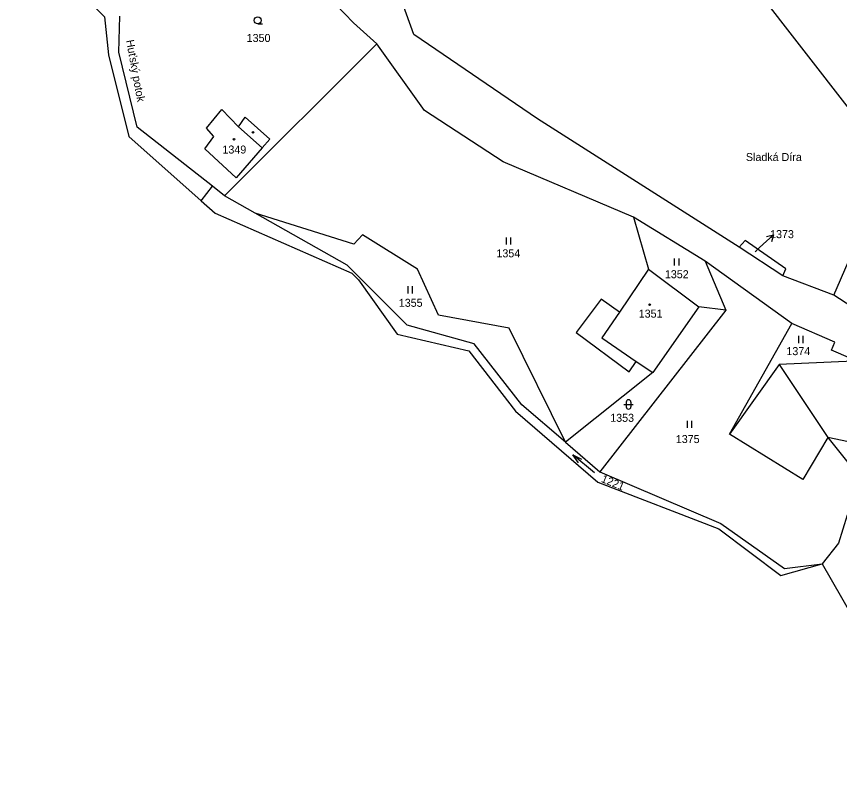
# Model space of a CAD drawing. Extents: x -670359 to -668019, y -978807 to -976674.
# Drawn here: x -669750.3 to -669575.5, y -978412.9 to -978251.2 of the extents above; entities that cross this region are included whole.
import ezdxf

# ---------------------------------------------------------------- set-up
doc = ezdxf.new("R2010")
doc.units = 0
for name, color, linetype in [('Hranice kat_území', 7, 'Continuous'), ('Hranice parcel', 7, 'Continuous'), ('Parcelní čísla', 7, 'Continuous'), ('Pop  PČ popisy', 7, 'Continuous'), ('Vnitřní kresba', 7, 'Continuous'), ('Značky budov', 7, 'Continuous'), ('Značky kultur', 7, 'Continuous')]:
    doc.layers.add(name, color=color, linetype=linetype)

msp = doc.modelspace()

# ---------------------------------------------------------------- linework, layer by layer
at = {"layer": 'Hranice kat_území'}
for points in [[(-669750.32, -978232.95), (-669731.63, -978251.32)], [(-669731.63, -978251.32), (-669730.74, -978259.36)], [(-669730.74, -978259.36), (-669726.47, -978276.74)], [(-669726.47, -978276.74), (-669711.08, -978290.39)], [(-669711.08, -978290.39), (-669708.1, -978293.03)], [(-669708.1, -978293.03), (-669679.08, -978305.78)], [(-669679.08, -978305.78), (-669677.68, -978307.17)], [(-669677.68, -978307.17), (-669669.42, -978318.74)], [(-669669.42, -978318.74), (-669654.21, -978322.24)], [(-669654.21, -978322.24), (-669644.3, -978335.07)], [(-669644.3, -978335.07), (-669626.85, -978350.14)], [(-669626.85, -978350.14), (-669601.13, -978360.04)], [(-669601.13, -978360.04), (-669587.99, -978369.95)], [(-669587.99, -978369.95), (-669579.21, -978367.53)], [(-669579.21, -978367.53), (-669553.11, -978412.89)]]:
    msp.add_lwpolyline(points, dxfattribs=at)
at = {"layer": 'Hranice parcel'}
for points in [[(-669572.87, -978271.54), (-669624.52, -978205.08)], [(-669678.72, -978252.62), (-669688.31, -978242.62)], [(-669665.94, -978255.08), (-669669.06, -978246.35)], [(-669728.54, -978258.84), (-669728.36, -978251.17)], [(-669673.74, -978257.07), (-669678.72, -978252.62)], [(-669639.64, -978272.98), (-669665.94, -978255.08)], [(-669673.74, -978257.07), (-669706.11, -978289.33)], [(-669663.64, -978271.2), (-669673.74, -978257.07)], [(-669724.71, -978274.79), (-669728.54, -978258.84)], [(-669709.95, -978274.94), (-669706.7, -978270.98)], [(-669706.7, -978270.98), (-669703.19, -978274.69)], [(-669646.94, -978282.1), (-669663.64, -978271.2)], [(-669703.19, -978274.69), (-669701.76, -978272.63)], [(-669701.76, -978272.63), (-669696.52, -978277.33)], [(-669596.79, -978300.24), (-669639.64, -978272.98)], [(-669708.68, -978287.32), (-669724.71, -978274.79)], [(-669708.4, -978276.74), (-669709.95, -978274.94)], [(-669710.31, -978279.34), (-669708.4, -978276.74)], [(-669696.52, -978277.33), (-669698.1, -978279.14)], [(-669576.72, -978310.45), (-669562.88, -978278.68)], [(-669703.65, -978285.49), (-669710.31, -978279.34)], [(-669698.1, -978279.14), (-669703.65, -978285.49)], [(-669619.29, -978293.84), (-669646.94, -978282.1)], [(-669706.11, -978289.33), (-669708.68, -978287.32)], [(-669699.59, -978293.03), (-669706.11, -978289.33)], [(-669678.67, -978299.6), (-669699.59, -978293.03)], [(-669680.09, -978304.1), (-669699.59, -978293.03)], [(-669604.02, -978303.2), (-669619.29, -978293.84)], [(-669619.29, -978293.84), (-669616.05, -978304.95)], [(-669676.81, -978297.62), (-669678.67, -978299.6)], [(-669665.12, -978304.94), (-669676.81, -978297.62)], [(-669595.57, -978298.81), (-669596.79, -978300.24)], [(-669586.91, -978304.83), (-669595.57, -978298.81)], [(-669587.56, -978306.34), (-669596.79, -978300.24)], [(-669585.65, -978316.43), (-669604.02, -978303.2)], [(-669604.02, -978303.2), (-669599.65, -978313.65)], [(-669667.35, -978316.79), (-669680.09, -978304.1)], [(-669660.66, -978314.67), (-669665.12, -978304.94)], [(-669616.05, -978304.95), (-669622.23, -978314.04)], [(-669616.05, -978304.95), (-669605.4, -978312.94)], [(-669587.56, -978306.34), (-669586.91, -978304.83)], [(-669576.72, -978310.45), (-669587.56, -978306.34)], [(-669626.12, -978311.28), (-669631.4, -978318.34)], [(-669622.23, -978314.04), (-669626.12, -978311.28)], [(-669562.62, -978319.59), (-669576.72, -978310.45)], [(-669599.65, -978313.65), (-669626.43, -978347.94)], [(-669605.4, -978312.94), (-669615.12, -978326.84)], [(-669599.65, -978313.65), (-669605.4, -978312.94)], [(-669645.64, -978317.47), (-669660.66, -978314.67)], [(-669653.12, -978320.8), (-669667.35, -978316.79)], [(-669598.89, -978339.97), (-669585.65, -978316.43)], [(-669576.5, -978320.45), (-669585.65, -978316.43)], [(-669633.68, -978341.69), (-669645.64, -978317.47)], [(-669631.4, -978318.34), (-669620.2, -978326.7)], [(-669577.23, -978322.1), (-669576.5, -978320.45)], [(-669642.94, -978333.74), (-669653.12, -978320.8)], [(-669573.09, -978323.91), (-669577.23, -978322.1)], [(-669620.2, -978326.7), (-669618.66, -978324.56)], [(-669618.66, -978324.56), (-669615.12, -978326.84)], [(-669588.32, -978325.13), (-669598.89, -978339.97)], [(-669567.79, -978324.26), (-669588.32, -978325.13)], [(-669615.12, -978326.84), (-669633.68, -978341.69)], [(-669633.68, -978341.69), (-669642.94, -978333.74)], [(-669552.68, -978345.99), (-669578, -978340.67)], [(-669578, -978340.67), (-669564.65, -978357.3)], [(-669633.68, -978341.69), (-669626.43, -978347.94)], [(-669626.43, -978347.94), (-669600.67, -978358.91)], [(-669573.85, -978357.2), (-669575.68, -978363.1)], [(-669600.67, -978358.91), (-669587.2, -978368.52)], [(-669575.68, -978363.1), (-669579.21, -978367.53)], [(-669587.2, -978368.52), (-669579.21, -978367.53)]]:
    msp.add_lwpolyline(points, dxfattribs=at)
at = {"layer": 'Parcelní čísla'}
for p, q in [((-669590.97, -978297.98), (-669589.5, -978297.66)), ((-669593.41, -978301.22), (-669592.46, -978300.35))]:
    msp.add_line(p, q, dxfattribs=at)
msp.add_lwpolyline([(-669592.46, -978300.35), (-669589.5, -978297.66), (-669589.96, -978299.09)], dxfattribs=at)
at = {"layer": 'Vnitřní kresba'}
for points in [[(-669703.19, -978274.69), (-669698.1, -978279.14)], [(-669711.08, -978290.39), (-669708.68, -978287.32)], [(-669622.23, -978314.04), (-669625.97, -978319.52)], [(-669625.97, -978319.52), (-669618.66, -978324.56)], [(-669588.32, -978325.13), (-669578, -978340.67)], [(-669583.3, -978349.58), (-669598.89, -978339.97)], [(-669578, -978340.67), (-669583.3, -978349.58)]]:
    msp.add_lwpolyline(points, dxfattribs=at)
at = {"layer": 'Značky budov'}
for centre in [(-669704.11, -978277.31), (-669615.83, -978312.47)]:
    msp.add_circle(centre, 0.175, dxfattribs=at)
at = {"layer": 'Značky kultur'}
for p, q in [((-669699.07, -978252.82), (-669698.07, -978252.82)), ((-669646.33, -978298.2), (-669646.33, -978299.7)), ((-669645.33, -978299.7), (-669645.33, -978298.2)), ((-669610.59, -978302.64), (-669610.59, -978304.14)), ((-669609.59, -978304.14), (-669609.59, -978302.64)), ((-669667.22, -978308.56), (-669667.22, -978310.06)), ((-669666.22, -978310.06), (-669666.22, -978308.56)), ((-669584.2, -978319.1), (-669584.2, -978320.6)), ((-669583.2, -978320.6), (-669583.2, -978319.1)), ((-669621.3, -978333.64), (-669619.3, -978333.64)), ((-669620.8, -978333.14), (-669620.8, -978334.14)), ((-669619.8, -978333.14), (-669619.8, -978334.14)), ((-669607.85, -978337.11), (-669607.85, -978338.61)), ((-669606.85, -978338.61), (-669606.85, -978337.11)), ((-669627.52, -978348.19), (-669632.14, -978344.37))]:
    msp.add_line(p, q, dxfattribs=at)
msp.add_lwpolyline([(-669630.92, -978346.03), (-669632.14, -978344.37), (-669630.28, -978345.26)], dxfattribs=at)
for centre, radius in [((-669699.07, -978252.07), 0.75), ((-669700.08, -978275.87), 0.175), ((-669704.11, -978277.31), 0.175), ((-669615.83, -978312.47), 0.175)]:
    msp.add_circle(centre, radius, dxfattribs=at)
for centre, start, end in [((-669620.3, -978333.14), 0, 180), ((-669620.3, -978334.14), 180, 0)]:
    msp.add_arc(centre, 0.5, start, end, dxfattribs=at)

# ---------------------------------------------------------------- texts
at = {"layer": 'Parcelní čísla'}
for s, height, p in [('1350', 1.7, (-669701.42, -978256.66)), ('1349', 1.7, (-669706.57, -978280.36)), ('1373', 1.7, (-669590.24, -978298.33)), ('1354', 1.7, (-669648.37, -978302.4)), ('1373', 0.1, (-669593.41, -978301.22)), ('1352', 1.7, (-669612.59, -978306.84)), ('1355', 1.7, (-669669.11, -978312.91)), ('1351', 1.7, (-669618.15, -978315.21)), ('1374', 1.7, (-669586.78, -978323.18)), ('1353', 1.7, (-669624.2, -978337.34)), ('1375', 1.7, (-669610.27, -978341.85))]:
    msp.add_text(s, height=height, dxfattribs=at).set_placement(p)
msp.add_text('1221', height=1.7, rotation=337.4902, dxfattribs=at).set_placement((-669626.28, -978350.06))
at = {"layer": 'Pop  PČ popisy'}
msp.add_text('Huťský potok', height=1.7, rotation=280.3752, dxfattribs=at).set_placement((-669727.05, -978256.35))
msp.add_text('Sladká Díra', height=1.7, dxfattribs=at).set_placement((-669595.38, -978281.95))

doc.saveas('drawing.dxf')
